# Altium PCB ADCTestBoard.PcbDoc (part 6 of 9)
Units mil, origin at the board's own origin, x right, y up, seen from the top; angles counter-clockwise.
Board outline 11022.62 x 9187 mil, 8 copper layers (TopLayer, InternalPlane1, InternalPlane2, InternalPlane3, InternalPlane4, InternalPlane5, MidLayer1, BottomLayer), stack 103.8 mil thick; 1282 components, 637 nets, 4473 pads, 1306 vias.
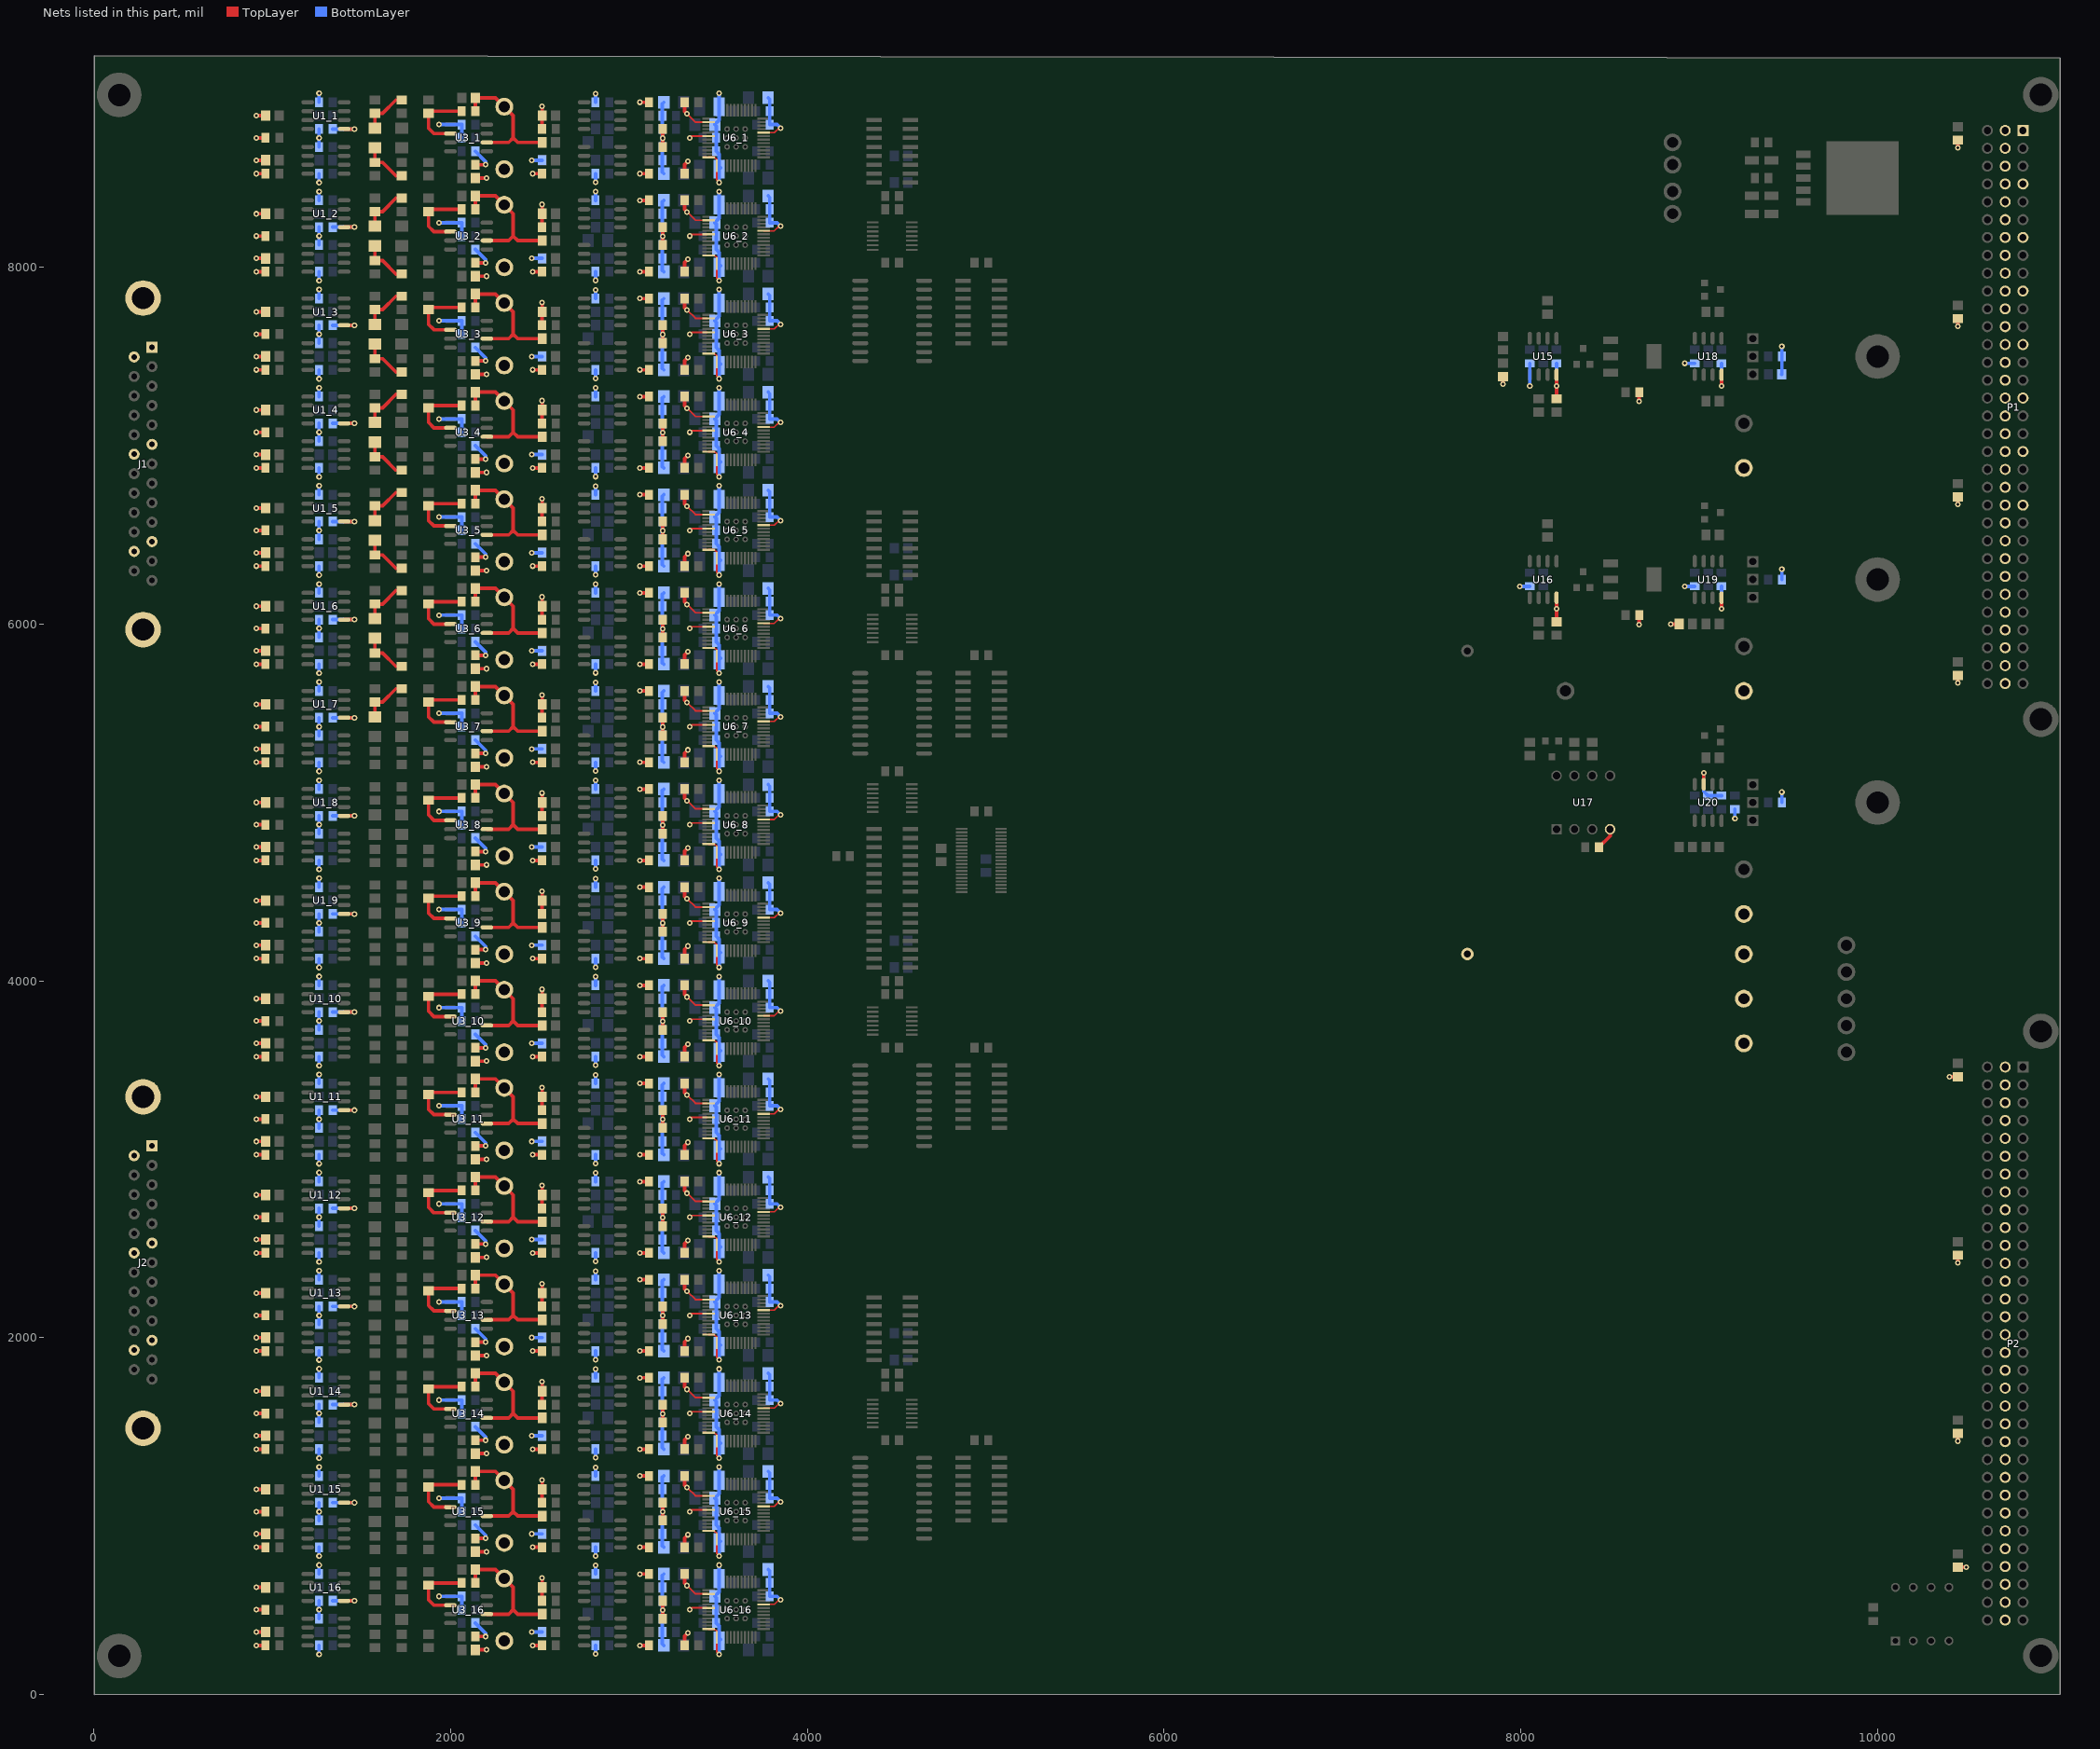
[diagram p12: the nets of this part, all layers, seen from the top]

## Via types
v1: diameter 32, hole 16, TopLayer to BottomLayer, 1306 vias

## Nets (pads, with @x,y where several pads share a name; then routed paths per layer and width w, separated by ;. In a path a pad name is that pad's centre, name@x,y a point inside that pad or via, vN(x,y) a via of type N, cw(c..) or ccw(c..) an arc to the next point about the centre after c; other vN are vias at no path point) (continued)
GND: C1_1.2 C1_2.2 C1_3.2 C1_4.2 C1_5.2 C1_6.2 C1_7.2 C1_8.2 C1_9.2 C1_10.2 C1_11.2 C1_12.2 C1_13.2 C1_14.2 C1_15.2 C1_16.2 C3_1.2 C3_2.2 C3_3.2 C3_4.2 C3_5.2 C3_6.2 C3_7.2 C3_8.2 C3_9.2 C3_10.2 C3_11.2 C3_12.2 C3_13.2 C3_14.2 C3_15.2 C3_16.2 C4_1.2 C4_2.2 C4_3.2 C4_4.2 C4_5.2 C4_6.2 C4_7.2 C4_8.2 C4_9.2 C4_10.2 C4_11.2 C4_12.2 C4_13.2 C4_14.2 C4_15.2 C4_16.2 C5_1.2 C5_2.2 C5_3.2 C5_4.2 C5_5.2 C5_6.2 C5_7.2 C5_8.2 C5_9.2 C5_10.2 C5_11.2 C5_12.2 C5_13.2 C5_14.2 C5_15.2 C5_16.2 C8_1.2 C8_2.2 C8_3.2 C8_4.2 C8_5.2 C8_6.2 C8_7.2 C8_8.2 C8_9.2 C8_10.2 C8_11.2 C8_12.2 C8_13.2 C8_14.2 C8_15.2 C8_16.2 C9_1.2 C9_2.2 C9_3.2 C9_4.2 C9_5.2 C9_6.2 C9_7.2 C9_8.2 C9_9.2 C9_10.2 C9_11.2 C9_12.2 C9_13.2 C9_14.2 C9_15.2 C9_16.2 C10_1.2 C10_2.2 C10_3.2 C10_4.2 C10_5.2 C10_6.2 C10_7.2 C10_8.2 C10_9.2 C10_10.2 C10_11.2 C10_12.2 C10_13.2 C10_14.2 C10_15.2 C10_16.2 C11_1.2 C11_2.2 C11_3.2 C11_4.2 C11_5.2 C11_6.2 C11_7.2 C11_8.2 C11_9.2 C11_10.2 C11_11.2 C11_12.2 C11_13.2 C11_14.2 C11_15.2 C11_16.2 C12_1.1 C12_2.1 C12_3.1 C12_4.1 C12_5.1 C12_6.1 C12_7.1 C12_8.1 C12_9.1 C12_10.1 C12_11.1 C12_12.1 C12_13.1 C12_14.1 C12_15.1 C12_16.1 C13_1.1 C13_2.1 C13_3.1 C13_4.1 C13_5.1 C13_6.1 C13_7.1 C13_8.1 C13_9.1 C13_10.1 C13_11.1 C13_12.1 C13_13.1 C13_14.1 C13_15.1 C13_16.1 C14_1.1 C14_2.1 C14_3.1 C14_4.1 C14_5.1 C14_6.1 C14_7.1 C14_8.1 C14_9.1 C14_10.1 C14_11.1 C14_12.1 C14_13.1 C14_14.1 C14_15.1 C14_16.1 C15_1.1 C15_2.1 C15_3.1 C15_4.1 C15_5.1 C15_6.1 C15_7.1 C15_8.1 C15_9.1 C15_10.1 C15_11.1 C15_12.1 C15_13.1 C15_14.1 C15_15.1 C15_16.1 C16_1.1 C16_2.1 C16_3.1 C16_4.1 C16_5.1 C16_6.1 C16_7.1 C16_8.1 C16_9.1 C16_10.1 C16_11.1 C16_12.1 C16_13.1 C16_14.1 C16_15.1 C16_16.1 C17_1.1 C17_2.1 C17_3.1 C17_4.1 C17_5.1 C17_6.1 C17_7.1 C17_8.1 C17_9.1 C17_10.1 C17_11.1 C17_12.1 C17_13.1 C17_14.1 C17_15.1 C17_16.1 C18_1.1 C18_2.1 C18_3.1 C18_4.1 C18_5.1 C18_6.1 C18_7.1 C18_8.1 C18_9.1 C18_10.1 C18_11.1 C18_12.1 C18_13.1 C18_14.1 C18_15.1 C18_16.1 C19_1.2 C19_2.2 C19_3.2 C19_4.2 C19_5.2 C19_6.2 C19_7.2 C19_8.2 C19_9.2 C19_10.2 C19_11.2 C19_12.2 C19_13.2 C19_14.2 C19_15.2 C19_16.2 C20_1.1 C20_2.1 C20_3.1 C20_4.1 C20_5.1 C20_6.1 C20_7.1 C20_8.1 C20_9.1 C20_10.1 C20_11.1 C20_12.1 C20_13.1 C20_14.1 C20_15.1 C20_16.1 C21_1.1 C21_2.1 C21_3.1 C21_4.1 C21_5.1 C21_6.1 C21_7.1 C21_8.1 C21_9.1 C21_10.1 C21_11.1 C21_12.1 C21_13.1 C21_14.1 C21_15.1 C21_16.1 C22_1.1 C22_2.1 C22_3.1 C22_4.1 C22_5.1 C22_6.1 C22_7.1 C22_8.1 C22_9.1 C22_10.1 C22_11.1 C22_12.1 C22_13.1 C22_14.1 C22_15.1 C22_16.1 C26_1.2 C26_2.2 C26_3.2 C26_4.2 C26_5.2 C26_6.2 C26_7.2 C26_8.2 C26_9.2 C26_10.2 C26_11.2 C26_12.2 C26_13.2 C26_14.2 C26_15.2 C26_16.2 C28_1.2 C28_2.2 C28_3.2 C28_4.2 C28_5.2 C28_6.2 C28_7.2 C28_8.2 C28_9.2 C28_10.2 C28_11.2 C28_12.2 C28_13.2 C28_14.2 C28_15.2 C28_16.2 C29_1.2 C29_2.2 C29_3.2 C29_4.2 C29_5.2 C29_6.2 C29_7.2 C29_8.2 C29_9.2 C29_10.2 C29_11.2 C29_12.2 C29_13.2 C29_14.2 C29_15.2 C29_16.2 C30_1.2 C30_2.2 C30_3.2 C30_4.2 C30_5.2 C30_6.2 C30_7.2 C30_8.2 C30_9.2 C30_10.2 C30_11.2 C30_12.2 C30_13.2 C30_14.2 C30_15.2 C30_16.2 C31_1.2 C31_2.2 C31_3.2 C31_4.2 C31_5.2 C31_6.2 C31_7.2 C31_8.2 C31_9.2 C31_10.2 C31_11.2 C31_12.2 C31_13.2 C31_14.2 C31_15.2 C31_16.2 C32_1.2 C32_2.2 C32_3.2 C32_4.2 C32_5.2 C32_6.2 C32_7.2 C32_8.2 C32_9.2 C32_10.2 C32_11.2 C32_12.2 C32_13.2 C32_14.2 C32_15.2 C32_16.2 C33_1.1 C33_2.1 C33_3.1 C33_4.1 C33_5.1 C33_6.1 C33_7.1 C33_8.1 C33_9.1 C33_10.1 C33_11.1 C33_12.1 C33_13.1 C33_14.1 C33_15.1 C33_16.1 C34_1.2 C34_2.2 C34_3.2 C34_4.2 C34_5.2 C34_6.2 C34_7.2 C34_8.2 C34_9.2 C34_10.2 C34_11.2 C34_12.2 C34_13.2 C34_14.2 C34_15.2 C34_16.2 C35_1.2 C35_2.2 C35_3.2 C35_4.2 C35_5.2 C35_6.2 C35_7.2 C35_8.2 C35_9.2 C35_10.2 C35_11.2 C35_12.2 C35_13.2 C35_14.2 C35_15.2 C35_16.2 C36_1.2 C36_2.2 C36_3.2 C36_4.2 C36_5.2 C36_6.2 C36_7.2 C36_8.2 C36_9.2 C36_10.2 C36_11.2 C36_12.2 C36_13.2 C36_14.2 C36_15.2 C36_16.2 C37_1.2 C37_2.2 C37_3.2 C37_4.2 C37_5.2 C37_6.2 C37_7.2 C37_8.2 C37_9.2 C37_10.2 C37_11.2 C37_12.2 C37_13.2 C37_14.2 C37_15.2 C37_16.2 C38_1.2 C38_2.2 C38_3.2 C38_4.2 C38_5.2 C38_6.2 C38_7.2 C38_8.2 C38_9.2 C38_10.2 C38_11.2 C38_12.2 C38_13.2 C38_14.2 C38_15.2 C38_16.2 C39_1.2 C39_2.2 C39_3.2 C39_4.2 C39_5.2 C39_6.2 C39_7.2 C39_8.2 C39_9.2 C39_10.2 C39_11.2 C39_12.2 C39_13.2 C39_14.2 C39_15.2 C39_16.2 C40_1.1 C40_2.1 C40_3.1 C40_4.1 C40_5.1 C40_6.1 C40_7.1 C40_8.1 C40_9.1 C40_10.1 C40_11.1 C40_12.1 C40_13.1 C40_14.1 C40_15.1 C40_16.1 C41_1.1 C41_2.1 C41_3.1 C41_4.1 C41_5.1 C41_6.1 C41_7.1 C41_8.1 C41_9.1 C41_10.1 C41_11.1 C41_12.1 C41_13.1 C41_14.1 C41_15.1 C41_16.1 C42_1.1 C42_2.1 C42_3.1 C42_4.1 C42_5.1 C42_6.1 C42_7.1 C42_8.1 C42_9.1 C42_10.1 C42_11.1 C42_12.1 C42_13.1 C42_14.1 C42_15.1 C42_16.1 C47.1 C48.2 C49.2 C50.1 C52.1 C53.2 C54.1 C55.2 C56.2 C57.2 C59.1 C60.2 C63.1 C64.1 C65.2 C80.1 J1.0 J1.1 J1.6 J1.11 J1.14 J1.19 J1.24 J2.0 J2.1 J2.6 J2.11 J2.14 J2.19 J2.24 P1.1A P1.1B P1.2B P1.3B P1.4A P1.4B P1.5B P1.6B P1.7A P1.7B P1.8B P1.9B P1.10A P1.10B P1.11B P1.12B P1.13A P1.13B P1.14B P1.15B P1.16A P1.16B P1.17B P1.18B P1.19A P1.19B P1.20B P1.21B P1.22A P1.22B P1.23B P1.24B P1.25B P1.26B P1.27B P1.28B P1.29B P1.30B P1.31B P1.32B P2.1B P2.2B P2.3B P2.4B P2.5B P2.6B P2.7B P2.8B P2.9B P2.10B P2.11B P2.12B P2.13B P2.14B P2.15B P2.16B P2.17B P2.18B P2.19B P2.20B P2.21B P2.22B P2.23B P2.24B P2.25B P2.26B P2.27B P2.28B P2.29B P2.30B P2.31B P2.32B R3_1.2 R3_2.2 R3_3.2 R3_4.2 R3_5.2 R3_6.2 R3_7.2 R3_8.2 R3_9.2 R3_10.2 R3_11.2 R3_12.2 R3_13.2 R3_14.2 R3_15.2 R3_16.2 R11_1.2 R11_2.2 R11_3.2 R11_4.2 R11_5.2 R11_6.2 R11_7.2 R11_8.2 R11_9.2 R11_10.2 R11_11.2 R11_12.2 R11_13.2 R11_14.2 R11_15.2 R11_16.2 R12_1.2 R12_2.2 R12_3.2 R12_4.2 R12_5.2 R12_6.2 R12_7.2 R12_8.2 R12_9.2 R12_10.2 R12_11.2 R12_12.2 R12_13.2 R12_14.2 R12_15.2 R12_16.2 R20_1.2 R20_2.2 R20_3.2 R20_4.2 R20_5.2 R20_6.2 R20_7.2 R20_8.2 R20_9.2 R20_10.2 R20_11.2 R20_12.2 R20_13.2 R20_14.2 R20_15.2 R20_16.2 R27.2 R30.1 R39.1 R41.1 R42.1 R45.1 R46.1 R47.1 R49.1 R50.1 R51.1 R52.1 R53.1 R54.1 TP2_1.1 TP2_2.1 TP2_3.1 TP2_4.1 TP2_5.1 TP2_6.1 TP2_7.1 TP2_8.1 TP2_9.1 TP2_10.1 TP2_11.1 TP2_12.1 TP2_13.1 TP2_14.1 TP2_15.1 TP2_16.1 TP13.1 TP14.1 TP15.1 TP16.1 TP17.1 TP18.1 U6_1.1 U6_1.20 U6_1.38 U6_1.42 U6_1.48 U6_2.1 U6_2.20 U6_2.38 U6_2.42 U6_2.48 U6_3.1 U6_3.20 U6_3.38 U6_3.42 U6_3.48 U6_4.1 U6_4.20 U6_4.38 U6_4.42 U6_4.48 U6_5.1 U6_5.20 U6_5.38 U6_5.42 U6_5.48 U6_6.1 U6_6.20 U6_6.38 U6_6.42 U6_6.48 U6_7.1 U6_7.20 U6_7.38 U6_7.42 U6_7.48 U6_8.1 U6_8.20 U6_8.38 U6_8.42 U6_8.48 U6_9.1 U6_9.20 U6_9.38 U6_9.42 U6_9.48 U6_10.1 U6_10.20 U6_10.38 U6_10.42 U6_10.48 U6_11.1 U6_11.20 U6_11.38 U6_11.42 U6_11.48 U6_12.1 U6_12.20 U6_12.38 U6_12.42 U6_12.48 U6_13.1 U6_13.20 U6_13.38 U6_13.42 U6_13.48 U6_14.1 U6_14.20 U6_14.38 U6_14.42 U6_14.48 U6_15.1 U6_15.20 U6_15.38 U6_15.42 U6_15.48 U6_16.1 U6_16.20 U6_16.38 U6_16.42 U6_16.48 U15.4 U16.4 U17.4 U18.4 U19.4 U20.7 | length 53519.9
  TopLayer w8: U6_16.20@3755,504.53 3814.53,504.53 3840,530 v1(3850,530) ; U6_15.20@3755,1054.53 3814.53,1054.53 3840,1080 v1(3850,1080) ; U6_14.20@3755,1604.53 3814.53,1604.53 3840,1630 v1(3850,1630) ; U6_13.20@3755,2154.53 3814.53,2154.53 3840,2180 v1(3850,2180) ; U6_12.20@3755,2704.53 3814.53,2704.53 3840,2730 v1(3850,2730) ; U6_11.20@3755,3254.53 3814.53,3254.53 3840,3280 v1(3850,3280) ; U6_10.20@3755,3804.53 3814.53,3804.53 3840,3830 v1(3850,3830) ; U6_9.20@3755,4354.53 3814.53,4354.53 3840,4380 v1(3850,4380) ; U6_8.20@3755,4904.53 3814.53,4904.53 3840,4930 v1(3850,4930) ; U6_7.20@3755,5454.53 3814.53,5454.53 3840,5480 v1(3850,5480) ; U6_6.20@3755,6004.53 3814.53,6004.53 3840,6030 v1(3850,6030) ; U6_5.20@3755,6554.53 3814.53,6554.53 3840,6580 v1(3850,6580) ; U6_4.20@3755,7104.53 3814.53,7104.53 3840,7130 v1(3850,7130) ; U6_3.20@3755,7654.53 3814.53,7654.53 3840,7680 v1(3850,7680) ; U6_2.20@3755,8204.53 3814.53,8204.53 3840,8230 v1(3850,8230) ; U6_1.20@3755,8754.53 3814.53,8754.53 3840,8780 v1(3850,8780)
  TopLayer w10: v1(3325,610) 3371.42,563.58 U6_16.38@3435.63,563.58 ; v1(3325,1160) 3371.42,1113.58 U6_15.38@3435.63,1113.58 ; v1(3325,1710) 3371.42,1663.58 U6_14.38@3435.63,1663.58 ; v1(3325,2260) 3371.42,2213.58 U6_13.38@3435.63,2213.58 ; v1(3325,2810) 3371.42,2763.58 U6_12.38@3435.63,2763.58 ; v1(3325,3360) 3371.42,3313.58 U6_11.38@3435.63,3313.58 ; v1(3325,3910) 3371.42,3863.58 U6_10.38@3435.63,3863.58 ; v1(3325,4460) 3371.42,4413.58 U6_9.38@3435.63,4413.58 ; v1(3325,5010) 3371.42,4963.58 U6_8.38@3435.63,4963.58 ; v1(3325,5560) 3371.42,5513.58 U6_7.38@3435.63,5513.58 ; v1(3325,6110) 3371.42,6063.58 U6_6.38@3435.63,6063.58 ; v1(3325,6660) 3371.42,6613.58 U6_5.38@3435.63,6613.58 ; v1(3325,7210) 3371.42,7163.58 U6_4.38@3435.63,7163.58 ; v1(3325,7760) 3371.42,7713.58 U6_3.38@3435.63,7713.58 ; v1(3325,8310) 3371.42,8263.58 U6_2.38@3435.63,8263.58 ; v1(3325,8860) 3371.42,8813.58 U6_1.38@3435.63,8813.58 ; v1(3340,475) 3349.84,484.84 U6_16.42@3435.63,484.84 ; v1(3340,1025) 3349.84,1034.84 U6_15.42@3435.63,1034.84 ; v1(3340,1575) 3349.84,1584.84 U6_14.42@3435.63,1584.84 ; v1(3340,2125) 3349.84,2134.84 U6_13.42@3435.63,2134.84 ; v1(3340,2675) 3349.84,2684.84 U6_12.42@3435.63,2684.84 ; v1(3340,3225) 3349.84,3234.84 U6_11.42@3435.63,3234.84 ; v1(3340,3775) 3349.84,3784.84 U6_10.42@3435.63,3784.84 ; v1(3340,4325) 3349.84,4334.84 U6_9.42@3435.63,4334.84 ; v1(3340,4875) 3349.84,4884.84 U6_8.42@3435.63,4884.84 ; v1(3340,5425) 3349.84,5434.84 U6_7.42@3435.63,5434.84 ; v1(3340,5975) 3349.84,5984.84 U6_6.42@3435.63,5984.84 ; v1(3340,6525) 3349.84,6534.84 U6_5.42@3435.63,6534.84 ; v1(3340,7075) 3349.84,7084.84 U6_4.42@3435.63,7084.84 ; v1(3340,7625) 3349.84,7634.84 U6_3.42@3435.63,7634.84 ; v1(3340,8175) 3349.84,8184.84 U6_2.42@3435.63,8184.84 ; v1(3340,8725) 3349.84,8734.84 U6_1.42@3435.63,8734.84 ; U6_16.48@3445,366.73 3478.27,366.73 3491.73,353.27 3491.73,238.5 v1(3505.12,225.12) ; U6_15.48@3445,916.73 3478.27,916.73 3491.73,903.27 3491.73,788.5 v1(3505.12,775.12) ; U6_14.48@3445,1466.73 3478.27,1466.73 3491.73,1453.27 3491.73,1338.5 v1(3505.12,1325.12) ; U6_13.48@3445,2016.73 3478.27,2016.73 3491.73,2003.27 3491.73,1888.5 v1(3505.12,1875.12) ; U6_12.48@3445,2566.73 3478.27,2566.73 3491.73,2553.27 3491.73,2438.5 v1(3505.12,2425.12) ; U6_11.48@3445,3116.73 3478.27,3116.73 3491.73,3103.27 3491.73,2988.5 v1(3505.12,2975.12) ; U6_10.48@3445,3666.73 3478.27,3666.73 3491.73,3653.27 3491.73,3538.5 v1(3505.12,3525.12) ; U6_9.48@3445,4216.73 3478.27,4216.73 3491.73,4203.27 3491.73,4088.5 v1(3505.12,4075.12) ; U6_8.48@3445,4766.73 3478.27,4766.73 3491.73,4753.27 3491.73,4638.5 v1(3505.12,4625.12) ; U6_7.48@3445,5316.73 3478.27,5316.73 3491.73,5303.27 3491.73,5188.5 v1(3505.12,5175.12) ; U6_6.48@3445,5866.73 3478.27,5866.73 3491.73,5853.27 3491.73,5738.5 v1(3505.12,5725.12) ; U6_5.48@3445,6416.73 3478.27,6416.73 3491.73,6403.27 3491.73,6288.5 v1(3505.12,6275.12) ; U6_4.48@3445,6966.73 3478.27,6966.73 3491.73,6953.27 3491.73,6838.5 v1(3505.12,6825.12) ; U6_3.48@3445,7516.73 3478.27,7516.73 3491.73,7503.27 3491.73,7388.5 v1(3505.12,7375.12) ; U6_2.48@3445,8066.73 3478.27,8066.73 3491.73,8053.27 3491.73,7938.5 v1(3505.12,7925.12) ; U6_1.48@3445,8616.73 3478.27,8616.73 3491.73,8603.27 3491.73,8488.5 v1(3505.12,8475.12)
  TopLayer w20: v1(910,275) C8_16.2@961.61,275 ; v1(910,350) R11_16.2@961.61,350 ; v1(910,475) C5_16.2@961.61,475 ; v1(910,600) R3_16.2@961.61,600 ; v1(910,825) C8_15.2@961.61,825 ; v1(910,900) R11_15.2@961.61,900 ; v1(910,1025) C5_15.2@961.61,1025 ; v1(910,1150) R3_15.2@961.61,1150 ; v1(910,1375) C8_14.2@961.61,1375 ; v1(910,1450) R11_14.2@961.61,1450 ; v1(910,1575) C5_14.2@961.61,1575 ; v1(910,1700) R3_14.2@961.61,1700 ; v1(910,1925) C8_13.2@961.61,1925 ; v1(910,2000) R11_13.2@961.61,2000 ; v1(910,2125) C5_13.2@961.61,2125 ; v1(910,2250) R3_13.2@961.61,2250 ; v1(910,2475) C8_12.2@961.61,2475 ; v1(910,2550) R11_12.2@961.61,2550 ; v1(910,2675) C5_12.2@961.61,2675 ; v1(910,2800) R3_12.2@961.61,2800 ; v1(910,3025) C8_11.2@961.61,3025 ; v1(910,3100) R11_11.2@961.61,3100 ; v1(910,3225) C5_11.2@961.61,3225 ; v1(910,3350) R3_11.2@961.61,3350 ; v1(910,3575) C8_10.2@961.61,3575 ; v1(910,3650) R11_10.2@961.61,3650 ; v1(910,3775) C5_10.2@961.61,3775 ; v1(910,3900) R3_10.2@961.61,3900 ; v1(910,4125) C8_9.2@961.61,4125 ; v1(910,4200) R11_9.2@961.61,4200 ; v1(910,4325) C5_9.2@961.61,4325 ; v1(910,4450) R3_9.2@961.61,4450 ; v1(910,4675) C8_8.2@961.61,4675 ; v1(910,4750) R11_8.2@961.61,4750 ; v1(910,4875) C5_8.2@961.61,4875 ; v1(910,5000) R3_8.2@961.61,5000 ; v1(910,5225) C8_7.2@961.61,5225 ; v1(910,5300) R11_7.2@961.61,5300 ; v1(910,5425) C5_7.2@961.61,5425 ; v1(910,5550) R3_7.2@961.61,5550 ; v1(910,5775) C8_6.2@961.61,5775 ; v1(910,5850) R11_6.2@961.61,5850 ; v1(910,5975) C5_6.2@961.61,5975 ; v1(910,6100) R3_6.2@961.61,6100 ; v1(910,6325) C8_5.2@961.61,6325 ; v1(910,6400) R11_5.2@961.61,6400 ; v1(910,6525) C5_5.2@961.61,6525 ; v1(910,6650) R3_5.2@961.61,6650 ; v1(910,6875) C8_4.2@961.61,6875 ; v1(910,6950) R11_4.2@961.61,6950 ; v1(910,7075) C5_4.2@961.61,7075 ; v1(910,7200) R3_4.2@961.61,7200 ; v1(910,7425) C8_3.2@961.61,7425 ; v1(910,7500) R11_3.2@961.61,7500 ; v1(910,7625) C5_3.2@961.61,7625 ; v1(910,7750) R3_3.2@961.61,7750 ; v1(910,7975) C8_2.2@961.61,7975 ; v1(910,8050) R11_2.2@961.61,8050 ; v1(910,8175) C5_2.2@961.61,8175 ; v1(910,8300) R3_2.2@961.61,8300 ; v1(910,8525) C8_1.2@961.61,8525 ; v1(910,8600) R11_1.2@961.61,8600 ; v1(910,8725) C5_1.2@961.61,8725 ; v1(910,8850) R3_1.2@961.61,8850 ; R12_16.2@2137.4,250 v1(2200,250) ; C12_16.1@2137.4,324.02 C12_16.1@2138.39,325 v1(2196.02,325) ; R12_15.2@2137.4,800 v1(2200,800) ; C12_15.1@2137.4,874.02 C12_15.1@2138.39,875 v1(2196.02,875) ; R12_14.2@2137.4,1350 v1(2200,1350) ; C12_14.1@2137.4,1424.02 C12_14.1@2138.39,1425 v1(2196.02,1425) ; R12_13.2@2137.4,1900 v1(2200,1900) ; C12_13.1@2137.4,1974.02 C12_13.1@2138.39,1975 v1(2196.02,1975) ; R12_12.2@2137.4,2450 v1(2200,2450) ; C12_12.1@2137.4,2524.02 C12_12.1@2138.39,2525 v1(2196.02,2525) ; R12_11.2@2137.4,3000 v1(2200,3000) ; C12_11.1@2137.4,3074.02 C12_11.1@2138.39,3075 v1(2196.02,3075) ; R12_10.2@2137.4,3550 v1(2200,3550) ; C12_10.1@2137.4,3624.02 C12_10.1@2138.39,3625 v1(2196.02,3625) ; R12_9.2@2137.4,4100 v1(2200,4100) ; C12_9.1@2137.4,4174.02 C12_9.1@2138.39,4175 v1(2196.02,4175) ; R12_8.2@2137.4,4650 v1(2200,4650) ; C12_8.1@2137.4,4724.02 C12_8.1@2138.39,4725 v1(2196.02,4725) ; R12_7.2@2137.4,5200 v1(2200,5200) ; C12_7.1@2137.4,5274.02 C12_7.1@2138.39,5275 v1(2196.02,5275) ; R12_6.2@2137.4,5750 v1(2200,5750) ; C12_6.1@2137.4,5824.02 C12_6.1@2138.39,5825 v1(2196.02,5825) ; R12_5.2@2137.4,6300 v1(2200,6300) ; C12_5.1@2137.4,6374.02 C12_5.1@2138.39,6375 v1(2196.02,6375) ; R12_4.2@2137.4,6850 v1(2200,6850) ; C12_4.1@2137.4,6924.02 C12_4.1@2138.39,6925 v1(2196.02,6925) ; R12_3.2@2137.4,7400 v1(2200,7400) ; C12_3.1@2137.4,7474.02 C12_3.1@2138.39,7475 v1(2196.02,7475) ; R12_2.2@2137.4,7950 v1(2200,7950) ; C12_2.1@2137.4,8024.02 C12_2.1@2138.39,8025 v1(2196.02,8025) ; R12_1.2@2137.4,8500 v1(2200,8500) ; C12_1.1@2137.4,8574.02 C12_1.1@2138.39,8575 v1(2196.02,8575) ; v1(2460,275) C28_16.2@2511.61,275 ; v1(2460,825) C28_15.2@2511.61,825 ; v1(2460,1375) C28_14.2@2511.61,1375 ; v1(2460,1925) C28_13.2@2511.61,1925 ; v1(2460,2475) C28_12.2@2511.61,2475 ; v1(2460,3025) C28_11.2@2511.61,3025 ; v1(2460,3575) C28_10.2@2511.61,3575 ; v1(2460,4125) C28_9.2@2511.61,4125 ; v1(2460,4675) C28_8.2@2511.61,4675 ; v1(2460,5225) C28_7.2@2511.61,5225 ; v1(2460,5775) C28_6.2@2511.61,5775 ; v1(2460,6325) C28_5.2@2511.61,6325 ; v1(2460,6875) C28_4.2@2511.61,6875 ; v1(2460,7425) C28_3.2@2511.61,7425 ; v1(2460,7975) C28_2.2@2511.61,7975 ; v1(2460,8525) C28_1.2@2511.61,8525 ; C39_16.2@2511.61,525 2511.61,599.02 R20_16.2@2512.6,600 v1(2512.6,652.4) ; C39_15.2@2511.61,1075 2511.61,1149.02 R20_15.2@2512.6,1150 v1(2512.6,1202.4) ; C39_14.2@2511.61,1625 2511.61,1699.02 R20_14.2@2512.6,1700 v1(2512.6,1752.4) ; C39_13.2@2511.61,2175 2511.61,2249.02 R20_13.2@2512.6,2250 v1(2512.6,2302.4) ; C39_12.2@2511.61,2725 2511.61,2799.02 R20_12.2@2512.6,2800 v1(2512.6,2852.4) ; C39_11.2@2511.61,3275 2511.61,3349.02 R20_11.2@2512.6,3350 v1(2512.6,3402.4) ; C39_10.2@2511.61,3825 2511.61,3899.02 R20_10.2@2512.6,3900 v1(2512.6,3952.4) ; C39_9.2@2511.61,4375 2511.61,4449.02 R20_9.2@2512.6,4450 v1(2512.6,4502.4) ; C39_8.2@2511.61,4925 2511.61,4999.02 R20_8.2@2512.6,5000 v1(2512.6,5052.4) ; C39_7.2@2511.61,5475 2511.61,5549.02 R20_7.2@2512.6,5550 v1(2512.6,5602.4) ; C39_6.2@2511.61,6025 2511.61,6099.02 R20_6.2@2512.6,6100 v1(2512.6,6152.4) ; C39_5.2@2511.61,6575 2511.61,6649.02 R20_5.2@2512.6,6650 v1(2512.6,6702.4) ; C39_4.2@2511.61,7125 2511.61,7199.02 R20_4.2@2512.6,7200 v1(2512.6,7252.4) ; C39_3.2@2511.61,7675 2511.61,7749.02 R20_3.2@2512.6,7750 v1(2512.6,7802.4) ; C39_2.2@2511.61,8225 2511.61,8299.02 R20_2.2@2512.6,8300 v1(2512.6,8352.4) ; C39_1.2@2511.61,8775 2511.61,8849.02 R20_1.2@2512.6,8850 v1(2512.6,8902.4) ; v1(3060,275) C26_16.2@3111.61,275 ; v1(3060,675) C36_16.2@3111.61,675 ; v1(3060,825) C26_15.2@3111.61,825 ; v1(3060,1225) C36_15.2@3111.61,1225 ; v1(3060,1375) C26_14.2@3111.61,1375 ; v1(3060,1775) C36_14.2@3111.61,1775 ; v1(3060,1925) C26_13.2@3111.61,1925 ; v1(3060,2325) C36_13.2@3111.61,2325 ; v1(3060,2475) C26_12.2@3111.61,2475 ; v1(3060,2875) C36_12.2@3111.61,2875 ; v1(3060,3025) C26_11.2@3111.61,3025 ; v1(3060,3425) C36_11.2@3111.61,3425 ; v1(3060,3575) C26_10.2@3111.61,3575 ; v1(3060,3975) C36_10.2@3111.61,3975 ; v1(3060,4125) C26_9.2@3111.61,4125 ; v1(3060,4525) C36_9.2@3111.61,4525 ; v1(3060,4675) C26_8.2@3111.61,4675 ; v1(3060,5075) C36_8.2@3111.61,5075 ; v1(3060,5225) C26_7.2@3111.61,5225 ; v1(3060,5625) C36_7.2@3111.61,5625 ; v1(3060,5775) C26_6.2@3111.61,5775 ; v1(3060,6175) C36_6.2@3111.61,6175 ; v1(3060,6325) C26_5.2@3111.61,6325 ; v1(3060,6725) C36_5.2@3111.61,6725 ; v1(3060,6875) C26_4.2@3111.61,6875 ; v1(3060,7275) C36_4.2@3111.61,7275 ; v1(3060,7425) C26_3.2@3111.61,7425 ; v1(3060,7825) C36_3.2@3111.61,7825 ; v1(3060,7975) C26_2.2@3111.61,7975 ; v1(3060,8375) C36_2.2@3111.61,8375 ; v1(3060,8525) C26_1.2@3111.61,8525 ; v1(3060,8925) C36_1.2@3111.61,8925 ; C38_16.2@3188.39,425 C37_16.2@3188.39,525 ; C38_15.2@3188.39,975 C37_15.2@3188.39,1075 ; C38_14.2@3188.39,1525 C37_14.2@3188.39,1625 ; C38_13.2@3188.39,2075 C37_13.2@3188.39,2175 ; C38_12.2@3188.39,2625 C37_12.2@3188.39,2725 ; C38_11.2@3188.39,3175 C37_11.2@3188.39,3275 ; C38_10.2@3188.39,3725 C37_10.2@3188.39,3825 ; C38_9.2@3188.39,4275 C37_9.2@3188.39,4375 ; C38_8.2@3188.39,4825 C37_8.2@3188.39,4925 ; C38_7.2@3188.39,5375 C37_7.2@3188.39,5475 ; C38_6.2@3188.39,5925 C37_6.2@3188.39,6025 ; C38_5.2@3188.39,6475 C37_5.2@3188.39,6575 ; C38_4.2@3188.39,7025 C37_4.2@3188.39,7125 ; C38_3.2@3188.39,7575 C37_3.2@3188.39,7675 ; C38_2.2@3188.39,8125 C37_2.2@3188.39,8225 ; C38_1.2@3188.39,8675 C37_1.2@3188.39,8775 ; C33_16.1@3311.61,275 3311.61,326.61 v1(3330,345) ; C32_16.2@3311.61,675 3311.61,623.39 v1(3325,610) ; C33_15.1@3311.61,825 3311.61,876.61 v1(3330,895) ; C32_15.2@3311.61,1225 3311.61,1173.39 v1(3325,1160) ; C33_14.1@3311.61,1375 3311.61,1426.61 v1(3330,1445) ; C32_14.2@3311.61,1775 3311.61,1723.39 v1(3325,1710) ; C33_13.1@3311.61,1925 3311.61,1976.61 v1(3330,1995) ; C32_13.2@3311.61,2325 3311.61,2273.39 v1(3325,2260) ; C33_12.1@3311.61,2475 3311.61,2526.61 v1(3330,2545) ; C32_12.2@3311.61,2875 3311.61,2823.39 v1(3325,2810) ; C33_11.1@3311.61,3025 3311.61,3076.61 v1(3330,3095) ; C32_11.2@3311.61,3425 3311.61,3373.39 v1(3325,3360) ; C33_10.1@3311.61,3575 3311.61,3626.61 v1(3330,3645) ; C32_10.2@3311.61,3975 3311.61,3923.39 v1(3325,3910) ; C33_9.1@3311.61,4125 3311.61,4176.61 v1(3330,4195) ; C32_9.2@3311.61,4525 3311.61,4473.39 v1(3325,4460) ; C33_8.1@3311.61,4675 3311.61,4726.61 v1(3330,4745) ; C32_8.2@3311.61,5075 3311.61,5023.39 v1(3325,5010) ; C33_7.1@3311.61,5225 3311.61,5276.61 v1(3330,5295) ; C32_7.2@3311.61,5625 3311.61,5573.39 v1(3325,5560) ; C33_6.1@3311.61,5775 3311.61,5826.61 v1(3330,5845) ; C32_6.2@3311.61,6175 3311.61,6123.39 v1(3325,6110) ; C33_5.1@3311.61,6325 3311.61,6376.61 v1(3330,6395) ; C32_5.2@3311.61,6725 3311.61,6673.39 v1(3325,6660) ; C33_4.1@3311.61,6875 3311.61,6926.61 v1(3330,6945) ; C32_4.2@3311.61,7275 3311.61,7223.39 v1(3325,7210) ; C33_3.1@3311.61,7425 3311.61,7476.61 v1(3330,7495) ; C32_3.2@3311.61,7825 3311.61,7773.39 v1(3325,7760) ; C33_2.1@3311.61,7975 3311.61,8026.61 v1(3330,8045) ; C32_2.2@3311.61,8375 3311.61,8323.39 v1(3325,8310) ; C33_1.1@3311.61,8525 3311.61,8576.61 v1(3330,8595) ; C32_1.2@3311.61,8925 3311.61,8873.39 v1(3325,8860) ; v1(7900,7345) R27.2@7900,7387.6 ; R49.1@8200,6012.4 U16.4@8200,6147.64 ; R30.1@8200,7262.4 U15.4@8200,7397.64 ; C52.1@8438.39,4750 8500,4811.61 U17.4@8500,4850 ; v1(8663.39,5997.6) C49.2@8663.39,6050 ; v1(8663.39,7247.6) C47.1@8663.39,7300 ; v1(8840,6000) R42.1@8887.6,6000 ; U20.7@9025,5102.36 v1(9025,5165) ; v1(9125,6085) U19.4@9125,6147.64 ; v1(9125,7335) U18.4@9125,7397.64 ; v1(10402.6,3462.6) R51.1@10450,3462.6 ; R54.1@10450,712.6 v1(10497.4,712.6) ; v1(10450,1420) R53.1@10450,1462.6 ; v1(10450,2420) R52.1@10450,2462.6 ; v1(10450,5670) R50.1@10450,5712.6 ; v1(10450,6670) R47.1@10450,6712.6 ; v1(10450,7670) R46.1@10450,7712.6 ; v1(10450,8670) R45.1@10450,8712.6
  BottomLayer w20: v1(1261.61,225) C11_16.2@1261.61,275 ; C19_16.2@1261.61,425 C4_16.2@1261.61,525 ; C1_16.2@1261.61,675 v1(1261.61,725) ; v1(1261.61,775) C11_15.2@1261.61,825 ; C19_15.2@1261.61,975 C4_15.2@1261.61,1075 ; C1_15.2@1261.61,1225 v1(1261.61,1275) ; v1(1261.61,1325) C11_14.2@1261.61,1375 ; C19_14.2@1261.61,1525 C4_14.2@1261.61,1625 ; C1_14.2@1261.61,1775 v1(1261.61,1825) ; v1(1261.61,1875) C11_13.2@1261.61,1925 ; C19_13.2@1261.61,2075 C4_13.2@1261.61,2175 ; C1_13.2@1261.61,2325 v1(1261.61,2375) ; v1(1261.61,2425) C11_12.2@1261.61,2475 ; C19_12.2@1261.61,2625 C4_12.2@1261.61,2725 ; C1_12.2@1261.61,2875 v1(1261.61,2925) ; v1(1261.61,2975) C11_11.2@1261.61,3025 ; C19_11.2@1261.61,3175 C4_11.2@1261.61,3275 ; C1_11.2@1261.61,3425 v1(1261.61,3475) ; v1(1261.61,3525) C11_10.2@1261.61,3575 ; C19_10.2@1261.61,3725 C4_10.2@1261.61,3825 ; C1_10.2@1261.61,3975 v1(1261.61,4025) ; v1(1261.61,4075) C11_9.2@1261.61,4125 ; C19_9.2@1261.61,4275 C4_9.2@1261.61,4375 ; C1_9.2@1261.61,4525 v1(1261.61,4575) ; v1(1261.61,4625) C11_8.2@1261.61,4675 ; C19_8.2@1261.61,4825 C4_8.2@1261.61,4925 ; C1_8.2@1261.61,5075 v1(1261.61,5125) ; v1(1261.61,5175) C11_7.2@1261.61,5225 ; C19_7.2@1261.61,5375 C4_7.2@1261.61,5475 ; C1_7.2@1261.61,5625 v1(1261.61,5675) ; v1(1261.61,5725) C11_6.2@1261.61,5775 ; C19_6.2@1261.61,5925 C4_6.2@1261.61,6025 ; C1_6.2@1261.61,6175 v1(1261.61,6225) ; v1(1261.61,6275) C11_5.2@1261.61,6325 ; C19_5.2@1261.61,6475 C4_5.2@1261.61,6575 ; C1_5.2@1261.61,6725 v1(1261.61,6775) ; v1(1261.61,6825) C11_4.2@1261.61,6875 ; C19_4.2@1261.61,7025 C4_4.2@1261.61,7125 ; C1_4.2@1261.61,7275 v1(1261.61,7325) ; v1(1261.61,7375) C11_3.2@1261.61,7425 ; C19_3.2@1261.61,7575 C4_3.2@1261.61,7675 ; C1_3.2@1261.61,7825 v1(1261.61,7875) ; v1(1261.61,7925) C11_2.2@1261.61,7975 ; C19_2.2@1261.61,8125 C4_2.2@1261.61,8225 ; C1_2.2@1261.61,8375 v1(1261.61,8425) ; v1(1261.61,8475) C11_1.2@1261.61,8525 ; C19_1.2@1261.61,8675 C4_1.2@1261.61,8775 ; C1_1.2@1261.61,8925 v1(1261.61,8975) ; v1(1935,550) C3_16.2@2061.61,550 C9_16.2@2061.61,475 ; v1(1935,1100) C3_15.2@2061.61,1100 C9_15.2@2061.61,1025 ; v1(1935,1650) C3_14.2@2061.61,1650 C9_14.2@2061.61,1575 ; v1(1935,2200) C3_13.2@2061.61,2200 C9_13.2@2061.61,2125 ; v1(1935,2750) C3_12.2@2061.61,2750 C9_12.2@2061.61,2675 ; v1(1935,3300) C3_11.2@2061.61,3300 C9_11.2@2061.61,3225 ; v1(1935,3850) C3_10.2@2061.61,3850 C9_10.2@2061.61,3775 ; v1(1935,4400) C3_9.2@2061.61,4400 C9_9.2@2061.61,4325 ; v1(1935,4950) C3_8.2@2061.61,4950 C9_8.2@2061.61,4875 ; v1(1935,5500) C3_7.2@2061.61,5500 C9_7.2@2061.61,5425 ; v1(1935,6050) C3_6.2@2061.61,6050 C9_6.2@2061.61,5975 ; v1(1935,6600) C3_5.2@2061.61,6600 C9_5.2@2061.61,6525 ; v1(1935,7150) C3_4.2@2061.61,7150 C9_4.2@2061.61,7075 ; v1(1935,7700) C3_3.2@2061.61,7700 C9_3.2@2061.61,7625 ; v1(1935,8250) C3_2.2@2061.61,8250 C9_2.2@2061.61,8175 ; v1(1935,8800) C3_1.2@2061.61,8800 C9_1.2@2061.61,8725 ; C10_16.2@2138.39,400 2196.02,342.36 v1(2196.02,325) ; C10_15.2@2138.39,950 2196.02,892.36 v1(2196.02,875) ; C10_14.2@2138.39,1500 2196.02,1442.36 v1(2196.02,1425) ; C10_13.2@2138.39,2050 2196.02,1992.36 v1(2196.02,1975) ; C10_12.2@2138.39,2600 2196.02,2542.36 v1(2196.02,2525) ; C10_11.2@2138.39,3150 2196.02,3092.36 v1(2196.02,3075) ; C10_10.2@2138.39,3700 2196.02,3642.36 v1(2196.02,3625) ; C10_9.2@2138.39,4250 2196.02,4192.36 v1(2196.02,4175) ; C10_8.2@2138.39,4800 2196.02,4742.36 v1(2196.02,4725) ; C10_7.2@2138.39,5350 2196.02,5292.36 v1(2196.02,5275) ; C10_6.2@2138.39,5900 2196.02,5842.36 v1(2196.02,5825) ; C10_5.2@2138.39,6450 2196.02,6392.36 v1(2196.02,6375) ; C10_4.2@2138.39,7000 2196.02,6942.36 v1(2196.02,6925) ; C10_3.2@2138.39,7550 2196.02,7492.36 v1(2196.02,7475) ; C10_2.2@2138.39,8100 2196.02,8042.36 v1(2196.02,8025) ; C10_1.2@2138.39,8650 2196.02,8592.36 v1(2196.02,8575) ; v1(2455,350) C34_16.2@2511.61,350 ; v1(2455,900) C34_15.2@2511.61,900 ; v1(2455,1450) C34_14.2@2511.61,1450 ; v1(2455,2000) C34_13.2@2511.61,2000 ; v1(2455,2550) C34_12.2@2511.61,2550 ; v1(2455,3100) C34_11.2@2511.61,3100 ; v1(2455,3650) C34_10.2@2511.61,3650 ; v1(2455,4200) C34_9.2@2511.61,4200 ; v1(2455,4750) C34_8.2@2511.61,4750 ; v1(2455,5300) C34_7.2@2511.61,5300 ; v1(2455,5850) C34_6.2@2511.61,5850 ; v1(2455,6400) C34_5.2@2511.61,6400 ; v1(2455,6950) C34_4.2@2511.61,6950 ; v1(2455,7500) C34_3.2@2511.61,7500 ; v1(2455,8050) C34_2.2@2511.61,8050 ; v1(2455,8600) C34_1.2@2511.61,8600 ; v1(2811.61,226.61) C30_16.2@2811.61,275 ; C29_16.2@2811.61,675 v1(2811.61,723.39) ; v1(2811.61,776.61) C30_15.2@2811.61,825 ; C29_15.2@2811.61,1225 v1(2811.61,1273.39) ; v1(2811.61,1326.61) C30_14.2@2811.61,1375 ; C29_14.2@2811.61,1775 v1(2811.61,1823.39) ; v1(2811.61,1876.61) C30_13.2@2811.61,1925 ; C29_13.2@2811.61,2325 v1(2811.61,2373.39) ; v1(2811.61,2426.61) C30_12.2@2811.61,2475 ; C29_12.2@2811.61,2875 v1(2811.61,2923.39) ; v1(2811.61,2976.61) C30_11.2@2811.61,3025 ; C29_11.2@2811.61,3425 v1(2811.61,3473.39) ; v1(2811.61,3526.61) C30_10.2@2811.61,3575 ; C29_10.2@2811.61,3975 v1(2811.61,4023.39) ; v1(2811.61,4076.61) C30_9.2@2811.61,4125 ; C29_9.2@2811.61,4525 v1(2811.61,4573.39) ; v1(2811.61,4626.61) C30_8.2@2811.61,4675 ; C29_8.2@2811.61,5075 v1(2811.61,5123.39) ; v1(2811.61,5176.61) C30_7.2@2811.61,5225 ; C29_7.2@2811.61,5625 v1(2811.61,5673.39) ; v1(2811.61,5726.61) C30_6.2@2811.61,5775 ; C29_6.2@2811.61,6175 v1(2811.61,6223.39) ; v1(2811.61,6276.61) C30_5.2@2811.61,6325 ; C29_5.2@2811.61,6725 v1(2811.61,6773.39) ; v1(2811.61,6826.61) C30_4.2@2811.61,6875 ; C29_4.2@2811.61,7275 v1(2811.61,7323.39) ; v1(2811.61,7376.61) C30_3.2@2811.61,7425 ; C29_3.2@2811.61,7825 v1(2811.61,7873.39) ; v1(2811.61,7926.61) C30_2.2@2811.61,7975 ; C29_2.2@2811.61,8375 v1(2811.61,8423.39) ; v1(2811.61,8476.61) C30_1.2@2811.61,8525 ; C29_1.2@2811.61,8925 v1(2811.61,8973.39) ; v1(3188.39,473.39) v1@3190,475 ; v1(3188.39,1023.39) v1@3190,1025 ; v1(3188.39,1573.39) v1@3190,1575 ; v1(3188.39,2123.39) v1@3190,2125 ; v1(3188.39,2673.39) v1@3190,2675 ; v1(3188.39,3223.39) v1@3190,3225 ; v1(3188.39,3773.39) v1@3190,3775 ; v1(3188.39,4323.39) v1@3190,4325 ; v1(3188.39,4873.39) v1@3190,4875 ; v1(3188.39,5423.39) v1@3190,5425 ; v1(3188.39,5973.39) v1@3190,5975 ; v1(3188.39,6523.39) v1@3190,6525 ; v1(3188.39,7073.39) v1@3190,7075 ; v1(3188.39,7623.39) v1@3190,7625 ; v1(3188.39,8173.39) v1@3190,8175 ; v1(3188.39,8723.39) v1@3190,8725 ; C40_16.1@3194.88,275 3186.61,283.27 3186.61,666.73 C20_16.1@3194.88,675 ; C40_15.1@3194.88,825 3186.61,833.27 3186.61,1216.73 C20_15.1@3194.88,1225 ; C40_14.1@3194.88,1375 3186.61,1383.27 3186.61,1766.73 C20_14.1@3194.88,1775 ; C40_13.1@3194.88,1925 3186.61,1933.27 3186.61,2316.73 C20_13.1@3194.88,2325 ; C40_12.1@3194.88,2475 3186.61,2483.27 3186.61,2866.73 C20_12.1@3194.88,2875 ; C40_11.1@3194.88,3025 3186.61,3033.27 3186.61,3416.73 C20_11.1@3194.88,3425 ; C40_10.1@3194.88,3575 3186.61,3583.27 3186.61,3966.73 C20_10.1@3194.88,3975 ; C40_9.1@3194.88,4125 3186.61,4133.27 3186.61,4516.73 C20_9.1@3194.88,4525 ; C40_8.1@3194.88,4675 3186.61,4683.27 3186.61,5066.73 C20_8.1@3194.88,5075 ; C40_7.1@3194.88,5225 3186.61,5233.27 3186.61,5616.73 C20_7.1@3194.88,5625 ; C40_6.1@3194.88,5775 3186.61,5783.27 3186.61,6166.73 C20_6.1@3194.88,6175 ; C40_5.1@3194.88,6325 3186.61,6333.27 3186.61,6716.73 C20_5.1@3194.88,6725 ; C40_4.1@3194.88,6875 3186.61,6883.27 3186.61,7266.73 C20_4.1@3194.88,7275 ; C40_3.1@3194.88,7425 3186.61,7433.27 3186.61,7816.73 C20_3.1@3194.88,7825 ; C40_2.1@3194.88,7975 3186.61,7983.27 3186.61,8366.73 C20_2.1@3194.88,8375 ; C40_1.1@3194.88,8525 3186.61,8533.27 3186.61,8916.73 C20_1.1@3194.88,8925 ; v1(3505.12,225.12) 3505.12,383.27 C15_16.1@3488.39,400 3488.39,541.73 C13_16.1@3480.12,550 3505.12,575 v1(3505.12,724.88) ; C35_16.2@3505.12,300 C35_16.2@3513.39,308.27 ; v1(3505.12,775.12) 3505.12,933.27 C15_15.1@3488.39,950 3488.39,1091.73 C13_15.1@3480.12,1100 3505.12,1125 v1(3505.12,1274.88) ; C35_15.2@3505.12,850 C35_15.2@3513.39,858.27 ; v1(3505.12,1325.12) 3505.12,1483.27 C15_14.1@3488.39,1500 3488.39,1641.73 C13_14.1@3480.12,1650 3505.12,1675 v1(3505.12,1824.88) ; C35_14.2@3505.12,1400 C35_14.2@3513.39,1408.27 ; v1(3505.12,1875.12) 3505.12,2033.27 C15_13.1@3488.39,2050 3488.39,2191.73 C13_13.1@3480.12,2200 3505.12,2225 v1(3505.12,2374.88) ; C35_13.2@3505.12,1950 C35_13.2@3513.39,1958.27 ; v1(3505.12,2425.12) 3505.12,2583.27 C15_12.1@3488.39,2600 3488.39,2741.73 C13_12.1@3480.12,2750 3505.12,2775 v1(3505.12,2924.88) ; C35_12.2@3505.12,2500 C35_12.2@3513.39,2508.27 ; v1(3505.12,2975.12) 3505.12,3133.27 C15_11.1@3488.39,3150 3488.39,3291.73 C13_11.1@3480.12,3300 3505.12,3325 v1(3505.12,3474.88) ; C35_11.2@3505.12,3050 C35_11.2@3513.39,3058.27 ; v1(3505.12,3525.12) 3505.12,3683.27 C15_10.1@3488.39,3700 3488.39,3841.73 C13_10.1@3480.12,3850 3505.12,3875 v1(3505.12,4024.88) ; C35_10.2@3505.12,3600 C35_10.2@3513.39,3608.27 ; v1(3505.12,4075.12) 3505.12,4233.27 C15_9.1@3488.39,4250 3488.39,4391.73 C13_9.1@3480.12,4400 3505.12,4425 v1(3505.12,4574.88) ; C35_9.2@3505.12,4150 C35_9.2@3513.39,4158.27 ; v1(3505.12,4625.12) 3505.12,4783.27 C15_8.1@3488.39,4800 3488.39,4941.73 C13_8.1@3480.12,4950 3505.12,4975 v1(3505.12,5124.88) ; C35_8.2@3505.12,4700 C35_8.2@3513.39,4708.27 ; v1(3505.12,5175.12) 3505.12,5333.27 C15_7.1@3488.39,5350 3488.39,5491.73 C13_7.1@3480.12,5500 3505.12,5525 v1(3505.12,5674.88) ; C35_7.2@3505.12,5250 C35_7.2@3513.39,5258.27 ; v1(3505.12,5725.12) 3505.12,5883.27 C15_6.1@3488.39,5900 3488.39,6041.73 C13_6.1@3480.12,6050 3505.12,6075 v1(3505.12,6224.88) ; C35_6.2@3505.12,5800 C35_6.2@3513.39,5808.27 ; v1(3505.12,6275.12) 3505.12,6433.27 C15_5.1@3488.39,6450 3488.39,6591.73 C13_5.1@3480.12,6600 3505.12,6625 v1(3505.12,6774.88) ; C35_5.2@3505.12,6350 C35_5.2@3513.39,6358.27 ; v1(3505.12,6825.12) 3505.12,6983.27 C15_4.1@3488.39,7000 3488.39,7141.73 C13_4.1@3480.12,7150 3505.12,7175 v1(3505.12,7324.88) ; C35_4.2@3505.12,6900 C35_4.2@3513.39,6908.27 ; v1(3505.12,7375.12) 3505.12,7533.27 C15_3.1@3488.39,7550 3488.39,7691.73 C13_3.1@3480.12,7700 3505.12,7725 v1(3505.12,7874.88) ; C35_3.2@3505.12,7450 C35_3.2@3513.39,7458.27 ; v1(3505.12,7925.12) 3505.12,8083.27 C15_2.1@3488.39,8100 3488.39,8241.73 C13_2.1@3480.12,8250 3505.12,8275 v1(3505.12,8424.88) ; C35_2.2@3505.12,8000 C35_2.2@3513.39,8008.27 ; v1(3505.12,8475.12) 3505.12,8633.27 C15_1.1@3488.39,8650 3488.39,8791.73 C13_1.1@3480.12,8800 3505.12,8825 v1(3505.12,8974.88) ; C35_1.2@3505.12,8550 C35_1.2@3513.39,8558.27 ; C18_16.1@3780.12,700 3788.39,691.73 C16_16.1@3788.39,550 3830,550 v1(3850,530) ; C18_15.1@3780.12,1250 3788.39,1241.73 C16_15.1@3788.39,1100 3830,1100 v1(3850,1080) ; C18_14.1@3780.12,1800 3788.39,1791.73 C16_14.1@3788.39,1650 3830,1650 v1(3850,1630) ; C18_13.1@3780.12,2350 3788.39,2341.73 C16_13.1@3788.39,2200 3830,2200 v1(3850,2180) ; C18_12.1@3780.12,2900 3788.39,2891.73 C16_12.1@3788.39,2750 3830,2750 v1(3850,2730) ; C18_11.1@3780.12,3450 3788.39,3441.73 C16_11.1@3788.39,3300 3830,3300 v1(3850,3280) ; C18_10.1@3780.12,4000 3788.39,3991.73 C16_10.1@3788.39,3850 3830,3850 v1(3850,3830) ; C18_9.1@3780.12,4550 3788.39,4541.73 C16_9.1@3788.39,4400 3830,4400 v1(3850,4380) ; C18_8.1@3780.12,5100 3788.39,5091.73 C16_8.1@3788.39,4950 3830,4950 v1(3850,4930) ; C18_7.1@3780.12,5650 3788.39,5641.73 C16_7.1@3788.39,5500 3830,5500 v1(3850,5480) ; C18_6.1@3780.12,6200 3788.39,6191.73 C16_6.1@3788.39,6050 3830,6050 v1(3850,6030) ; C18_5.1@3780.12,6750 3788.39,6741.73 C16_5.1@3788.39,6600 3830,6600 v1(3850,6580) ; C18_4.1@3780.12,7300 3788.39,7291.73 C16_4.1@3788.39,7150 3830,7150 v1(3850,7130) ; C18_3.1@3780.12,7850 3788.39,7841.73 C16_3.1@3788.39,7700 3830,7700 v1(3850,7680) ; C18_2.1@3780.12,8400 3788.39,8391.73 C16_2.1@3788.39,8250 3830,8250 v1(3850,8230) ; C18_1.1@3780.12,8950 3788.39,8941.73 C16_1.1@3788.39,8800 3830,8800 v1(3850,8780) ; v1(7993.39,6211.61) C80.1@8050,6211.61 ; v1(8050,7335) C50.1@8050,7461.61 ; v1(8200,7335) C48.2@8200,7461.61 ; v1(8918.39,6211.61) C60.2@8975,6211.61 ; v1(8918.39,7461.61) C59.1@8975,7461.61 ; v1(9025,5165) 9025,5062.4 R41.1@9050,5037.4 9050.98,5038.39 C64.1@9125,5038.39 ; v1(9125,6085) C57.2@9125,6211.61 ; v1(9125,7335) C56.2@9125,7461.61 ; v1(9200,4910) C63.1@9200,4961.61 ; R39.1@9462.4,7400 9463.39,7400.98 v1(9463.39,7557.6) ; C65.2@9463.39,5000 v1(9463.39,5057.6) ; C55.2@9463.39,6250 v1(9463.39,6307.6)
  other v1: 1261.61,475 1261.61,1025 1261.61,1575 1261.61,2125 1261.61,2675 1261.61,3225 1261.61,3775 1261.61,4325 1261.61,4875 1261.61,5425 1261.61,5975 8200,6085 1261.61,6525 1261.61,7075 1261.61,7625 1261.61,8175 1261.61,8725
NetC2_1_1: C2_1.1 R2_1.2 R17_1.1 TP1_1.1 U3_1.6 | length 785.4
  TopLayer w20: C2_1.1@2138.39,8875 2138.39,8949.02 R2_1.2@2137.4,8950 2250,8950 2350,8850 2350,8725 ; U3_1.6@2202.36,8700 2325,8700 2350,8725 ; R17_1.1@2512.6,8700 2375,8700 2350,8725
NetC2_1_2: C2_1.2 R6_1.2 U3_1.2 | length 409.4
  TopLayer w20: U3_1.2@1997.64,8750 1905,8750 1875,8780 R6_1.2@1875,8862.6 1887.4,8875 C2_1.2@2061.61,8875
NetC2_2_1: C2_2.1 R2_2.2 R17_2.1 TP1_2.1 U3_2.6 | length 785.4
  TopLayer w20: C2_2.1@2138.39,8325 2138.39,8399.02 R2_2.2@2137.4,8400 2250,8400 2350,8300 2350,8175 ; U3_2.6@2202.36,8150 2325,8150 2350,8175 ; R17_2.1@2512.6,8150 2375,8150 2350,8175
NetC2_2_2: C2_2.2 R6_2.2 U3_2.2 | length 409.4
  TopLayer w20: U3_2.2@1997.64,8200 1905,8200 1875,8230 R6_2.2@1875,8312.6 1887.4,8325 C2_2.2@2061.61,8325
NetC2_3_1: C2_3.1 R2_3.2 R17_3.1 TP1_3.1 U3_3.6 | length 785.4
  TopLayer w20: C2_3.1@2138.39,7775 2138.39,7849.02 R2_3.2@2137.4,7850 2250,7850 2350,7750 2350,7625 ; U3_3.6@2202.36,7600 2325,7600 2350,7625 ; R17_3.1@2512.6,7600 2375,7600 2350,7625
NetC2_3_2: C2_3.2 R6_3.2 U3_3.2 | length 409.4
  TopLayer w20: U3_3.2@1997.64,7650 1905,7650 1875,7680 R6_3.2@1875,7762.6 1887.4,7775 C2_3.2@2061.61,7775
NetC2_4_1: C2_4.1 R2_4.2 R17_4.1 TP1_4.1 U3_4.6 | length 785.4
  TopLayer w20: C2_4.1@2138.39,7225 2138.39,7299.02 R2_4.2@2137.4,7300 2250,7300 2350,7200 2350,7075 ; U3_4.6@2202.36,7050 2325,7050 2350,7075 ; R17_4.1@2512.6,7050 2375,7050 2350,7075
NetC2_4_2: C2_4.2 R6_4.2 U3_4.2 | length 409.4
  TopLayer w20: U3_4.2@1997.64,7100 1905,7100 1875,7130 R6_4.2@1875,7212.6 1887.4,7225 C2_4.2@2061.61,7225
NetC2_5_1: C2_5.1 R2_5.2 R17_5.1 TP1_5.1 U3_5.6 | length 785.4
  TopLayer w20: C2_5.1@2138.39,6675 2138.39,6749.02 R2_5.2@2137.4,6750 2250,6750 2350,6650 2350,6525 ; U3_5.6@2202.36,6500 2325,6500 2350,6525 ; R17_5.1@2512.6,6500 2375,6500 2350,6525
NetC2_5_2: C2_5.2 R6_5.2 U3_5.2 | length 409.4
  TopLayer w20: U3_5.2@1997.64,6550 1905,6550 1875,6580 R6_5.2@1875,6662.6 1887.4,6675 C2_5.2@2061.61,6675
NetC2_6_1: C2_6.1 R2_6.2 R17_6.1 TP1_6.1 U3_6.6 | length 785.4
  TopLayer w20: C2_6.1@2138.39,6125 2138.39,6199.02 R2_6.2@2137.4,6200 2250,6200 2350,6100 2350,5975 ; U3_6.6@2202.36,5950 2325,5950 2350,5975 ; R17_6.1@2512.6,5950 2375,5950 2350,5975
NetC2_6_2: C2_6.2 R6_6.2 U3_6.2 | length 409.4
  TopLayer w20: U3_6.2@1997.64,6000 1905,6000 1875,6030 R6_6.2@1875,6112.6 1887.4,6125 C2_6.2@2061.61,6125
NetC2_7_1: C2_7.1 R2_7.2 R17_7.1 TP1_7.1 U3_7.6 | length 785.4
  TopLayer w20: C2_7.1@2138.39,5575 2138.39,5649.02 R2_7.2@2137.4,5650 2250,5650 2350,5550 2350,5425 ; U3_7.6@2202.36,5400 2325,5400 2350,5425 ; R17_7.1@2512.6,5400 2375,5400 2350,5425
NetC2_7_2: C2_7.2 R6_7.2 U3_7.2 | length 409.4
  TopLayer w20: U3_7.2@1997.64,5450 1905,5450 1875,5480 R6_7.2@1875,5562.6 1887.4,5575 C2_7.2@2061.61,5575
NetC2_8_1: C2_8.1 R2_8.2 R17_8.1 TP1_8.1 U3_8.6 | length 785.4
  TopLayer w20: C2_8.1@2138.39,5025 2138.39,5099.02 R2_8.2@2137.4,5100 2250,5100 2350,5000 2350,4875 ; U3_8.6@2202.36,4850 2325,4850 2350,4875 ; R17_8.1@2512.6,4850 2375,4850 2350,4875
NetC2_8_2: C2_8.2 R6_8.2 U3_8.2 | length 409.4
  TopLayer w20: U3_8.2@1997.64,4900 1905,4900 1875,4930 R6_8.2@1875,5012.6 1887.4,5025 C2_8.2@2061.61,5025
NetC2_9_1: C2_9.1 R2_9.2 R17_9.1 TP1_9.1 U3_9.6 | length 785.4
  TopLayer w20: C2_9.1@2138.39,4475 2138.39,4549.02 R2_9.2@2137.4,4550 2250,4550 2350,4450 2350,4325 ; U3_9.6@2202.36,4300 2325,4300 2350,4325 ; R17_9.1@2512.6,4300 2375,4300 2350,4325
NetC2_9_2: C2_9.2 R6_9.2 U3_9.2 | length 409.4
  TopLayer w20: U3_9.2@1997.64,4350 1905,4350 1875,4380 R6_9.2@1875,4462.6 1887.4,4475 C2_9.2@2061.61,4475
NetC2_10_1: C2_10.1 R2_10.2 R17_10.1 TP1_10.1 U3_10.6 | length 785.4
  TopLayer w20: C2_10.1@2138.39,3925 2138.39,3999.02 R2_10.2@2137.4,4000 2250,4000 2350,3900 2350,3775 ; U3_10.6@2202.36,3750 2325,3750 2350,3775 ; R17_10.1@2512.6,3750 2375,3750 2350,3775
NetC2_10_2: C2_10.2 R6_10.2 U3_10.2 | length 409.4
  TopLayer w20: U3_10.2@1997.64,3800 1905,3800 1875,3830 R6_10.2@1875,3912.6 1887.4,3925 C2_10.2@2061.61,3925
NetC2_11_1: C2_11.1 R2_11.2 R17_11.1 TP1_11.1 U3_11.6 | length 785.4
  TopLayer w20: C2_11.1@2138.39,3375 2138.39,3449.02 R2_11.2@2137.4,3450 2250,3450 2350,3350 2350,3225 ; U3_11.6@2202.36,3200 2325,3200 2350,3225 ; R17_11.1@2512.6,3200 2375,3200 2350,3225
NetC2_11_2: C2_11.2 R6_11.2 U3_11.2 | length 409.4
  TopLayer w20: U3_11.2@1997.64,3250 1905,3250 1875,3280 R6_11.2@1875,3362.6 1887.4,3375 C2_11.2@2061.61,3375
NetC2_12_1: C2_12.1 R2_12.2 R17_12.1 TP1_12.1 U3_12.6 | length 785.4
  TopLayer w20: C2_12.1@2138.39,2825 2138.39,2899.02 R2_12.2@2137.4,2900 2250,2900 2350,2800 2350,2675 ; U3_12.6@2202.36,2650 2325,2650 2350,2675 ; R17_12.1@2512.6,2650 2375,2650 2350,2675
NetC2_12_2: C2_12.2 R6_12.2 U3_12.2 | length 409.4
  TopLayer w20: U3_12.2@1997.64,2700 1905,2700 1875,2730 R6_12.2@1875,2812.6 1887.4,2825 C2_12.2@2061.61,2825
NetC2_13_1: C2_13.1 R2_13.2 R17_13.1 TP1_13.1 U3_13.6 | length 785.4
  TopLayer w20: C2_13.1@2138.39,2275 2138.39,2349.02 R2_13.2@2137.4,2350 2250,2350 2350,2250 2350,2125 ; U3_13.6@2202.36,2100 2325,2100 2350,2125 ; R17_13.1@2512.6,2100 2375,2100 2350,2125
NetC2_13_2: C2_13.2 R6_13.2 U3_13.2 | length 409.4
  TopLayer w20: U3_13.2@1997.64,2150 1905,2150 1875,2180 R6_13.2@1875,2262.6 1887.4,2275 C2_13.2@2061.61,2275
NetC2_14_1: C2_14.1 R2_14.2 R17_14.1 TP1_14.1 U3_14.6 | length 785.4
  TopLayer w20: C2_14.1@2138.39,1725 2138.39,1799.02 R2_14.2@2137.4,1800 2250,1800 2350,1700 2350,1575 ; U3_14.6@2202.36,1550 2325,1550 2350,1575 ; R17_14.1@2512.6,1550 2375,1550 2350,1575
NetC2_14_2: C2_14.2 R6_14.2 U3_14.2 | length 409.4
  TopLayer w20: U3_14.2@1997.64,1600 1905,1600 1875,1630 R6_14.2@1875,1712.6 1887.4,1725 C2_14.2@2061.61,1725
NetC2_15_1: C2_15.1 R2_15.2 R17_15.1 TP1_15.1 U3_15.6 | length 785.4
  TopLayer w20: C2_15.1@2138.39,1175 2138.39,1249.02 R2_15.2@2137.4,1250 2250,1250 2350,1150 2350,1025 ; U3_15.6@2202.36,1000 2325,1000 2350,1025 ; R17_15.1@2512.6,1000 2375,1000 2350,1025
NetC2_15_2: C2_15.2 R6_15.2 U3_15.2 | length 409.4
  TopLayer w20: U3_15.2@1997.64,1050 1905,1050 1875,1080 R6_15.2@1875,1162.6 1887.4,1175 C2_15.2@2061.61,1175
NetC2_16_1: C2_16.1 R2_16.2 R17_16.1 TP1_16.1 U3_16.6 | length 785.4
  TopLayer w20: C2_16.1@2138.39,625 2138.39,699.02 R2_16.2@2137.4,700 2250,700 2350,600 2350,475 ; U3_16.6@2202.36,450 2325,450 2350,475 ; R17_16.1@2512.6,450 2375,450 2350,475
NetC2_16_2: C2_16.2 R6_16.2 U3_16.2 | length 409.4
  TopLayer w20: U3_16.2@1997.64,500 1905,500 1875,530 R6_16.2@1875,612.6 1887.4,625 C2_16.2@2061.61,625
NetC4_1_1: C4_1.1 U1_1.5 | length 179.3
  TopLayer w20: U1_1.5@1402.36,8775 v1(1460,8775)
  BottomLayer w20: C4_1.1@1338.39,8775 v1(1460,8775)
NetC4_2_1: C4_2.1 U1_2.5 | length 179.3
  TopLayer w20: U1_2.5@1402.36,8225 v1(1460,8225)
  BottomLayer w20: C4_2.1@1338.39,8225 v1(1460,8225)
NetC4_3_1: C4_3.1 U1_3.5 | length 179.3
  TopLayer w20: U1_3.5@1402.36,7675 v1(1460,7675)
  BottomLayer w20: C4_3.1@1338.39,7675 v1(1460,7675)
NetC4_4_1: C4_4.1 U1_4.5 | length 179.3
  TopLayer w20: U1_4.5@1402.36,7125 v1(1460,7125)
  BottomLayer w20: C4_4.1@1338.39,7125 v1(1460,7125)
NetC4_5_1: C4_5.1 U1_5.5 | length 179.3
  TopLayer w20: U1_5.5@1402.36,6575 v1(1460,6575)
  BottomLayer w20: C4_5.1@1338.39,6575 v1(1460,6575)
NetC4_6_1: C4_6.1 U1_6.5 | length 179.3
  TopLayer w20: U1_6.5@1402.36,6025 v1(1460,6025)
  BottomLayer w20: C4_6.1@1338.39,6025 v1(1460,6025)
NetC4_7_1: C4_7.1 U1_7.5 | length 179.3
  TopLayer w20: U1_7.5@1402.36,5475 v1(1460,5475)
  BottomLayer w20: C4_7.1@1338.39,5475 v1(1460,5475)
NetC4_8_1: C4_8.1 U1_8.5 | length 179.3
  TopLayer w20: U1_8.5@1402.36,4925 v1(1460,4925)
  BottomLayer w20: C4_8.1@1338.39,4925 v1(1460,4925)
NetC4_9_1: C4_9.1 U1_9.5 | length 179.3
  TopLayer w20: U1_9.5@1402.36,4375 v1(1460,4375)
  BottomLayer w20: C4_9.1@1338.39,4375 v1(1460,4375)
NetC4_10_1: C4_10.1 U1_10.5 | length 179.3
  TopLayer w20: U1_10.5@1402.36,3825 v1(1460,3825)
  BottomLayer w20: C4_10.1@1338.39,3825 v1(1460,3825)
NetC4_11_1: C4_11.1 U1_11.5 | length 179.3
  TopLayer w20: U1_11.5@1402.36,3275 v1(1460,3275)
  BottomLayer w20: C4_11.1@1338.39,3275 v1(1460,3275)
NetC4_12_1: C4_12.1 U1_12.5 | length 179.3
  TopLayer w20: U1_12.5@1402.36,2725 v1(1460,2725)
  BottomLayer w20: C4_12.1@1338.39,2725 v1(1460,2725)
NetC4_13_1: C4_13.1 U1_13.5 | length 179.3
  TopLayer w20: U1_13.5@1402.36,2175 v1(1460,2175)
  BottomLayer w20: C4_13.1@1338.39,2175 v1(1460,2175)
NetC4_14_1: C4_14.1 U1_14.5 | length 179.3
  TopLayer w20: U1_14.5@1402.36,1625 v1(1460,1625)
  BottomLayer w20: C4_14.1@1338.39,1625 v1(1460,1625)
NetC4_15_1: C4_15.1 U1_15.5 | length 179.3
  TopLayer w20: U1_15.5@1402.36,1075 v1(1460,1075)
  BottomLayer w20: C4_15.1@1338.39,1075 v1(1460,1075)
NetC4_16_1: C4_16.1 U1_16.5 | length 179.3
  TopLayer w20: U1_16.5@1402.36,525 v1(1460,525)
  BottomLayer w20: C4_16.1@1338.39,525 v1(1460,525)
NetC6_1_1: C6_1.1 R4_1.2 R5_1.1 | length 230.9
  TopLayer w20: C6_1.1@1575,8780.12 R4_1.2@1575,8862.6 1617.6,8862.6 1692.4,8937.4
NetC6_1_2: C6_1.2 R9_1.2 R10_1.1 | length 230.9
  TopLayer w20: C6_1.2@1575,8669.88 R9_1.2@1575,8587.4 1617.6,8587.4 1692.4,8512.6
NetC6_2_1: C6_2.1 R4_2.2 R5_2.1 | length 230.9
  TopLayer w20: C6_2.1@1575,8230.12 R4_2.2@1575,8312.6 1617.6,8312.6 1692.4,8387.4
NetC6_2_2: C6_2.2 R9_2.2 R10_2.1 | length 230.9
  TopLayer w20: C6_2.2@1575,8119.88 R9_2.2@1575,8037.4 1617.6,8037.4 1692.4,7962.6
NetC6_3_1: C6_3.1 R4_3.2 R5_3.1 | length 230.9
  TopLayer w20: C6_3.1@1575,7680.12 R4_3.2@1575,7762.6 1617.6,7762.6 1692.4,7837.4
NetC6_3_2: C6_3.2 R9_3.2 R10_3.1 | length 230.9
  TopLayer w20: C6_3.2@1575,7569.88 R9_3.2@1575,7487.4 1617.6,7487.4 1692.4,7412.6
NetC6_4_1: C6_4.1 R4_4.2 R5_4.1 | length 230.9
  TopLayer w20: C6_4.1@1575,7130.12 R4_4.2@1575,7212.6 1617.6,7212.6 1692.4,7287.4
NetC6_4_2: C6_4.2 R9_4.2 R10_4.1 | length 230.9
  TopLayer w20: C6_4.2@1575,7019.88 R9_4.2@1575,6937.4 1617.6,6937.4 1692.4,6862.6
NetC6_5_1: C6_5.1 R4_5.2 R5_5.1 | length 230.9
  TopLayer w20: C6_5.1@1575,6580.12 R4_5.2@1575,6662.6 1617.6,6662.6 1692.4,6737.4
NetC6_5_2: C6_5.2 R9_5.2 R10_5.1 | length 230.9
  TopLayer w20: C6_5.2@1575,6469.88 R9_5.2@1575,6387.4 1617.6,6387.4 1692.4,6312.6
NetC6_6_1: C6_6.1 R4_6.2 R5_6.1 | length 230.9
  TopLayer w20: C6_6.1@1575,6030.12 R4_6.2@1575,6112.6 1617.6,6112.6 1692.4,6187.4
NetC6_6_2: C6_6.2 R9_6.2 R10_6.1 | length 230.9
  TopLayer w20: C6_6.2@1575,5919.88 R9_6.2@1575,5837.4 1617.6,5837.4 1692.4,5762.6
NetC6_7_1: C6_7.1 R4_7.2 R5_7.1 | length 230.9
  TopLayer w20: C6_7.1@1575,5480.12 R4_7.2@1575,5562.6 1617.6,5562.6 1692.4,5637.4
